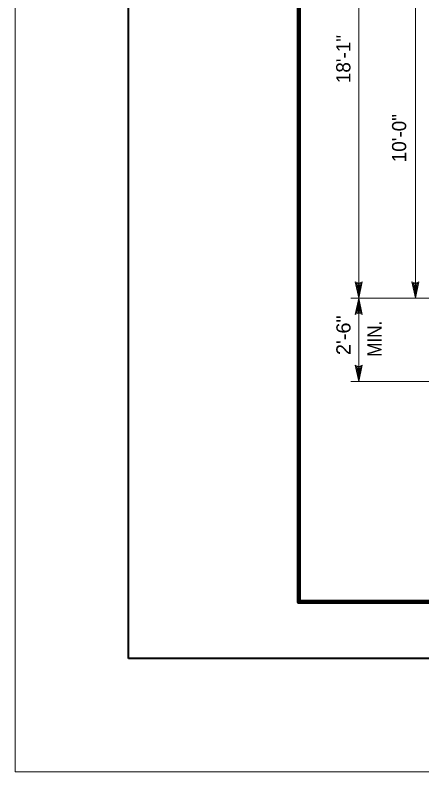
# Model space of a CAD drawing. Extents: x -22.3 to 19.7, y -11.8 to 18.2.
# Drawn here: x -22.31 to -18.72, y -11.84 to -5.16 of the extents above; entities that cross this region are included whole.
import ezdxf
from ezdxf.enums import TextEntityAlignment as Align

# ---------------------------------------------------------------- set-up
doc = ezdxf.new("R2010")
doc.units = 0
doc.header["$LTSCALE"] = 0.05
doc.layers.add('1', color=7, linetype='Continuous', lineweight=13)

msp = doc.modelspace()

# ---------------------------------------------------------------- linework, layer by layer
at = {"layer": '1'}
for p, q in [((-22.30942, -11.83969), (-22.30942, 18.16031)), ((-19.27942, -7.65769), (-19.31042, -7.51369)), ((-19.27942, -7.62069), (-19.29942, -7.52669)), ((-19.29942, -7.52669), (-19.27942, -7.53569)), ((-19.27942, -7.58469), (-19.28942, -7.53969)), ((-19.28942, -7.53969), (-19.27942, -7.54369)), ((-19.27942, -7.65769), (-19.24842, -7.51369)), ((-19.27942, -7.62069), (-19.25942, -7.52669)), ((-19.27942, -7.53569), (-19.25942, -7.52669)), ((-19.27942, -7.58469), (-19.27042, -7.53969)), ((-19.27942, -7.54369), (-19.27042, -7.53969)), ((-18.78042, -7.65769), (-18.81142, -7.51369)), ((-18.78042, -7.62069), (-18.80042, -7.52669)), ((-18.80042, -7.52669), (-18.78042, -7.53569)), ((-18.78042, -7.58469), (-18.79042, -7.53969)), ((-18.79042, -7.53969), (-18.78042, -7.54369)), ((-18.78042, -7.65769), (-18.74942, -7.51369)), ((-18.78042, -7.62069), (-18.76042, -7.52669)), ((-18.78042, -7.53569), (-18.76042, -7.52669)), ((-18.78042, -7.58469), (-18.77142, -7.53969)), ((-18.78042, -7.54369), (-18.77142, -7.53969)), ((-18.11842, -7.65769), (-19.34842, -7.65769)), ((-19.27942, -7.65769), (-19.31042, -7.80169)), ((-19.27942, -7.65769), (-19.24842, -7.80169)), ((-19.27942, -7.69469), (-19.29942, -7.78869)), ((-19.27942, -7.73069), (-19.28842, -7.77569)), ((-19.27942, -7.69469), (-19.25942, -7.78869)), ((-19.27942, -7.73069), (-19.26942, -7.77569)), ((-19.27942, -7.77969), (-19.29942, -7.78869)), ((-19.27942, -7.77169), (-19.28842, -7.77569)), ((-19.26942, -7.77569), (-19.27942, -7.77169)), ((-19.25942, -7.78869), (-19.27942, -7.77969)), ((-19.27942, -8.39369), (-19.31042, -8.24969)), ((-19.27942, -8.35669), (-19.29942, -8.26269)), ((-19.29942, -8.26269), (-19.27942, -8.27169)), ((-19.27942, -8.32069), (-19.28942, -8.27569)), ((-19.28942, -8.27569), (-19.27942, -8.27969)), ((-19.27942, -8.39369), (-19.24842, -8.24969)), ((-19.27942, -8.35669), (-19.25942, -8.26269)), ((-19.27942, -8.27169), (-19.25942, -8.26269)), ((-19.27942, -8.32069), (-19.27042, -8.27569)), ((-19.27942, -8.27969), (-19.27042, -8.27569)), ((-18.07742, -8.39369), (-19.34842, -8.39369)), ((19.69058, -11.83969), (-22.30942, -11.83969))]:
    msp.add_line(p, q, dxfattribs=at)
at = {"layer": '1', "lineweight": 40}
msp.add_lwpolyline([(-21.30942, -10.83969), (-21.30942, 17.16031), (18.69058, 17.16031), (18.69058, -10.83969)], close=True, dxfattribs=at)
at = {"layer": '1', "lineweight": 90}
msp.add_lwpolyline([(-19.80942, 16.66031), (18.19058, 16.66031), (18.19058, -10.33969), (-19.80942, -10.33969)], close=True, dxfattribs=at)
at = {"layer": '1'}
for points in [[(-19.27942, -8.39369), (-19.27942, -7.65769), (-19.27942, -3.12369)], [(-18.78042, -7.65769), (-18.78042, -4.99969), (-18.78042, -4.74969), (-18.78042, -3.12169)], [(-19.31042, -7.51369), (-19.27942, -7.52769), (-19.24842, -7.51369)], [(-18.81142, -7.51369), (-18.78042, -7.52769), (-18.74942, -7.51369)], [(-19.24842, -7.80169), (-19.27942, -7.78769), (-19.31042, -7.80169)], [(-19.31042, -8.24969), (-19.27942, -8.26369), (-19.24842, -8.24969)]]:
    msp.add_lwpolyline(points, dxfattribs=at)

# ---------------------------------------------------------------- texts
for s, p in [('18\'-1"', (-19.35342, -5.76169)), ('10\'-0"', (-18.86142, -6.45969))]:
    msp.add_text(s, height=0.125, rotation=90, dxfattribs=at).set_placement(p)
for s, width, p in [('2\'-6"', 1.05, (-19.35242, -7.98619)), ('MIN.', 0.9, (-19.07842, -8.01619))]:
    msp.add_text(s, height=0.125, rotation=90, dxfattribs=dict(at, width=width)).set_placement(p, align=Align.CENTER)

doc.saveas('drawing.dxf')
